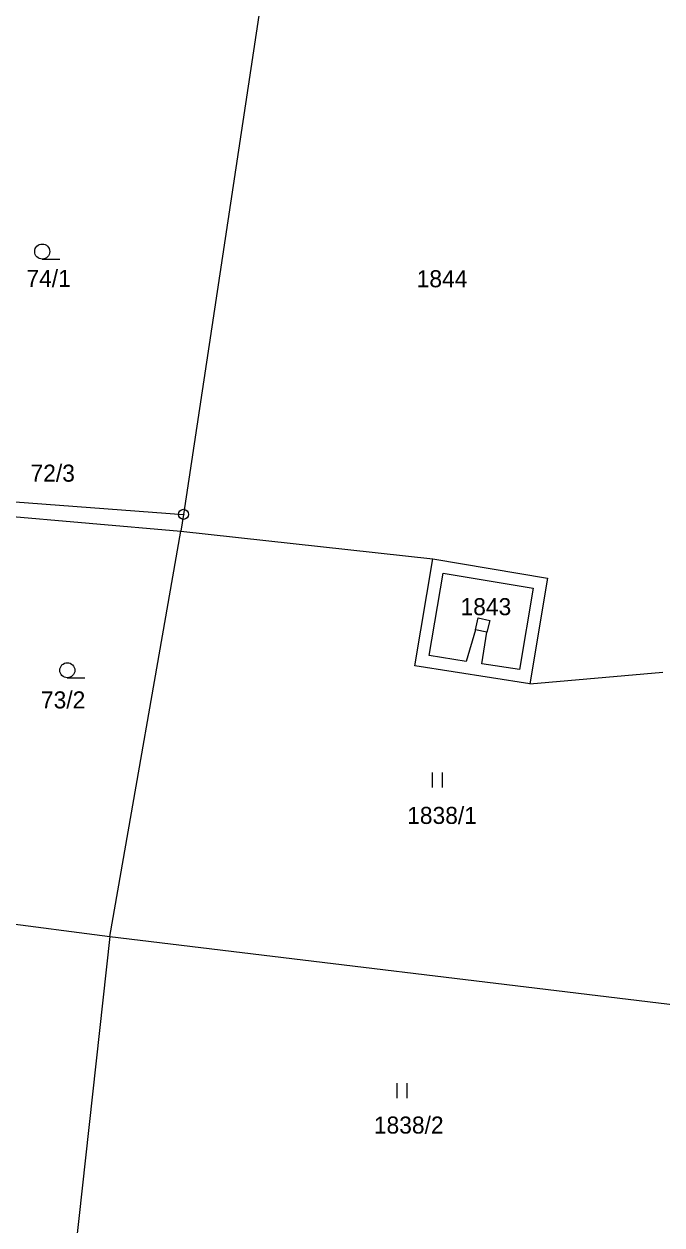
# Model space of a CAD drawing. Extents: x -601131 to -597152, y -1058536 to -1055911.
# Drawn here: x -599354.1 to -599290.5, y -1057055.1 to -1056935.4 of the extents above; entities that cross this region are included whole.
import ezdxf
from ezdxf.enums import TextEntityAlignment as Align

# ---------------------------------------------------------------- set-up
doc = ezdxf.new("R2010")
doc.units = 0
doc.header["$LTSCALE"] = 0.68
for name, color, linetype, lineweight in [('1', 7, 'Continuous', 25), ('3', 7, 'Continuous', 25), ('4', 7, 'Continuous', 13), ('8', 7, 'Continuous', 25)]:
    doc.layers.add(name, color=color, linetype=linetype, lineweight=lineweight)
doc.layers.add('2', color=7, linetype='Continuous')

msp = doc.modelspace()

# ---------------------------------------------------------------- linework, layer by layer
at = {"layer": '1'}
for p, q in [((-599330.17, -1056930.88), (-599338.23, -1056984.23)), ((-599400.68, -1056980.47), (-599338.49, -1056985.92)), ((-599387.3, -1056980.59), (-599338.23, -1056984.23)), ((-599338.23, -1056984.23), (-599338.49, -1056985.92)), ((-599345.57, -1057026.31), (-599338.49, -1056985.92)), ((-599338.49, -1056985.92), (-599313.37, -1056988.67)), ((-599315.17, -1056999.34), (-599313.37, -1056988.67)), ((-599313.37, -1056988.67), (-599301.96, -1056990.6)), ((-599301.96, -1056990.6), (-599303.7, -1057001.12)), ((-599303.7, -1057001.12), (-599315.17, -1056999.34)), ((-599303.7, -1057001.12), (-599290.46, -1056999.96)), ((-599374.96, -1057022.46), (-599345.57, -1057026.31)), ((-599345.57, -1057026.31), (-599349.02, -1057057.72)), ((-599345.57, -1057026.31), (-599286.77, -1057033.4))]:
    msp.add_line(p, q, dxfattribs=at)
at = {"layer": '3'}
for p, q in [((-599352.313, -1056958.79), (-599350.563, -1056958.79)), ((-599349.813, -1057000.52), (-599348.063, -1057000.52)), ((-599313.401, -1057011.45), (-599313.401, -1057009.95)), ((-599312.4, -1057011.45), (-599312.4, -1057009.95)), ((-599316.931, -1057042.41), (-599316.931, -1057040.91)), ((-599315.93, -1057042.41), (-599315.93, -1057040.91))]:
    msp.add_line(p, q, dxfattribs=at)
for centre in [(-599352.3129, -1056958.0398), (-599349.8129, -1056999.7698)]:
    msp.add_circle(centre, 0.75, dxfattribs=at)
at = {"layer": '4'}
for p, q in [((-599313.76, -1056998.29), (-599312.36, -1056990.09)), ((-599312.36, -1056990.09), (-599303.38, -1056991.6)), ((-599303.38, -1056991.6), (-599304.74, -1056999.68)), ((-599309.13, -1056995.74), (-599308.86, -1056994.55)), ((-599308.86, -1056994.55), (-599307.7, -1056994.81)), ((-599307.7, -1056994.81), (-599307.98, -1056995.98)), ((-599309.13, -1056995.74), (-599310.05, -1056998.9)), ((-599307.98, -1056995.98), (-599309.13, -1056995.74)), ((-599308.49, -1056999.14), (-599307.98, -1056995.98)), ((-599310.05, -1056998.9), (-599313.76, -1056998.29)), ((-599304.74, -1056999.68), (-599308.49, -1056999.14))]:
    msp.add_line(p, q, dxfattribs=at)
at = {"layer": '8'}
for radius in [0.5, 0.0303]:
    msp.add_circle((-599338.23, -1056984.2299), radius, dxfattribs=at)

# ---------------------------------------------------------------- texts
at = {"layer": '2'}
for s, p in [('74/1', (-599353.89, -1056961.574)), ('72/3', (-599353.48, -1056980.975)), ('73/2', (-599352.44, -1057003.574))]:
    msp.add_text(s, height=1.7, dxfattribs=at).set_placement(p)
for s, p in [('1844', (-599312.46, -1056961.602)), ('1843', (-599308.09, -1056994.282)), ('1838/1', (-599312.46, -1057015.084)), ('1838/2', (-599315.78, -1057045.945))]:
    msp.add_text(s, height=1.7, dxfattribs=at).set_placement(p, align=Align.CENTER)

doc.saveas('drawing.dxf')
